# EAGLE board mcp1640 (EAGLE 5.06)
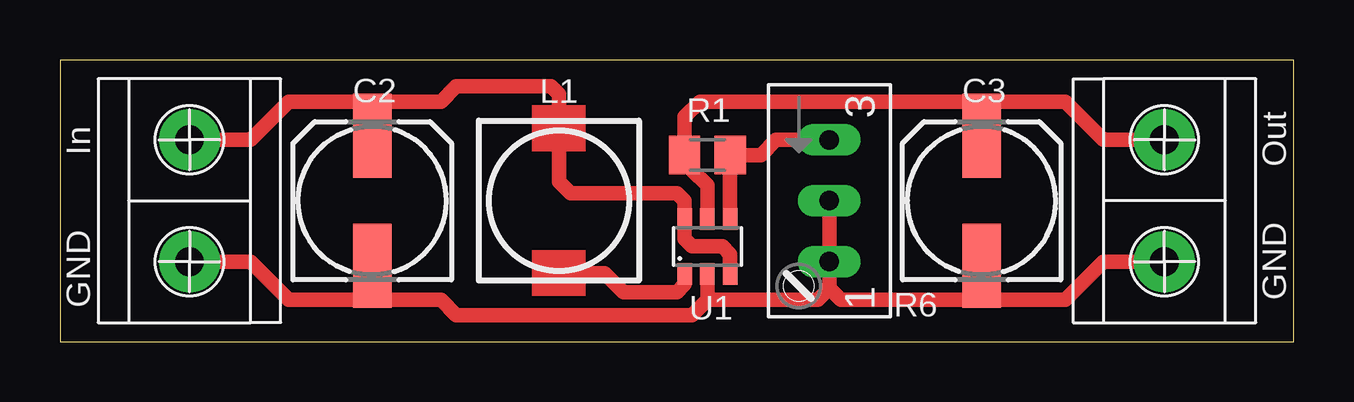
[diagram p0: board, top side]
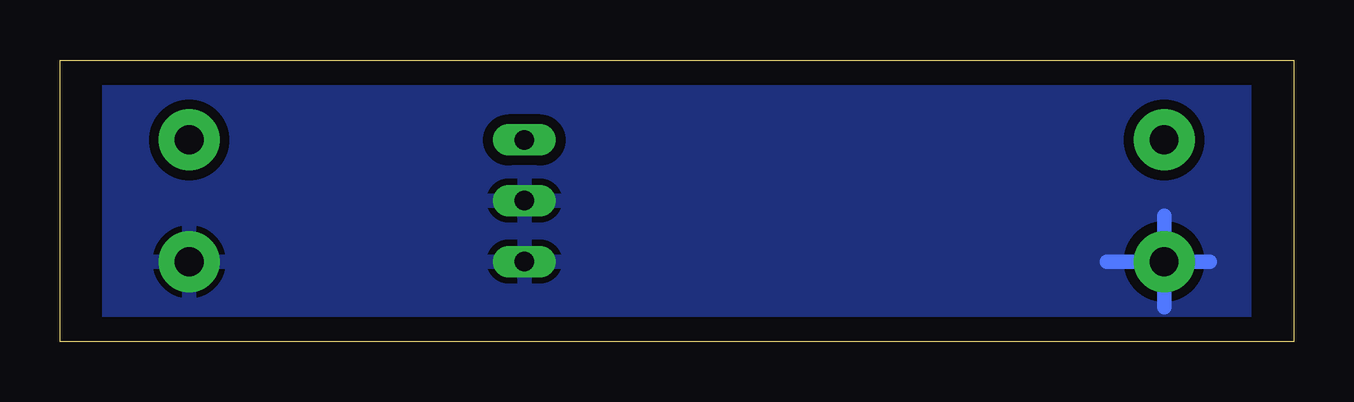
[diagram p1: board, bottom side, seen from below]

Size 51.42 x 11.74 mm. Coordinates in mm from the lower left corner, seen from the top.
Outline: 0,0 51.42,0 51.42,11.74 0,11.74 0,0
Copper layers (1*16): Top 0.035mm / dielectric 1.5mm / Bottom 0.035mm
Design rules "default": minimum track width 10mil, minimum drill 24mil, track to track 8mil, track to pad 8mil, pad to pad 8mil, via to via 8mil, smd to smd 8mil, copper to edge 40mil, drill to drill 8mil, minimum pad ring 10mil, minimum via ring 8mil, stop-mask expansion 4mil, vias tented up to drill 0mil, thermal gap 10mil

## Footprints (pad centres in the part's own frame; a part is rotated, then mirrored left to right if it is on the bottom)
153CLV-0605 = smd 3.5 x 1.6: + 2.7,0; - -2.7,0
M0805 = smd 1.3 x 1.6: 1 -0.95,0; 2 0.95,0
S64W = drill 0.813 long: A 2.54,1.27; E -2.54,1.27; S 0,1.27
SOT23-6 = smd 0.6 x 0.9: 1 -0.95,-1.15; 2 0,-1.15; 3 0.95,-1.15; 4 0.95,1.15; 5 0,1.15; 6 -0.95,1.15
ARK2 = drill 1.2 pad 2.54 round: 1 -2.54,0; 3 2.54,0 | drill 0.8 pad 2.54 round: 2 2.54,0

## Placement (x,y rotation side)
C2  4,7uF  [153CLV-0605]  13.02,5.87 90 top
C3  10uF  [153CLV-0605]  38.42,5.87 90 top
R1  1M  [M0805]  26.99,7.78 180 top
R6  1M  [S64W]  30.8,5.87 270 top
U1  93AA76A  [SOT23-6]  26.99,3.97 0 top
U$1  ARK2  [ARK2]  5.4,5.87 270 top
U$2  ARK2  [ARK2]  46.04,5.87 90 top

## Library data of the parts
C2 C3 R1 = rcl
R6 = pot
U1 = mcp1640
U$1 U$2 = ark2

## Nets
GND: C2.- C3.- R6.A R6.S U1.2 U$1.2 U$2.1
N$1: C2.+ U1.3 U1.6 U$1.1
N$2: U1.1
N$4: C3.+ R1.2 U1.5 U$2.2
N$5: R1.1 R6.E U1.4

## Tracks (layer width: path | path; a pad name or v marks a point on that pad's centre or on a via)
GND
  Top 0.61: 26.99,1.75 26.35,1.11 16.51,1.11 15.88,1.75 13.02,1.75 C2.- 13.02,2.06 12.7,1.75 9.53,1.75 7.94,3.33 U$1.2 | R6.S R6.A 32.07,2.22 | 26.99,1.75 U1.2 | 26.99,1.75 31.59,1.75 32.07,2.22 | 32.07,2.22 32.54,1.75 38.42,1.75 C3.- 38.42,2.06 38.73,1.75 41.91,1.75 43.5,3.33 U$2.1
  Bottom 0.61: U$1.2 5.4,5.24 | U$1.2 5.4,1.43 | U$1.2 7.78,3.33 | 3.49,3.33 U$1.2
  pour Bottom (isolate 0.406): 2.06,12.22 2.06,-0.48 49.37,-0.48 49.37,12.22
N$1
  Top 0.61: U1.3 27.94,3.65 27.62,3.97 26.35,3.97 26.04,4.29 U1.6 | U1.6 | 13.02,10 9.53,10 7.94,8.41 U$1.1 | U1.6 26.04,5.87 25.72,6.19 21.27,6.19 20.8,6.67 20.8,10.32 20.48,10.64 16.51,10.64 15.88,10 13.02,10 | 13.02,10 C2.+
N$2
  Top 0.61: U1.1 26.04,2.38 25.72,2.06 23.5,2.06 22.7,2.86 20.8,2.86
N$4
  Top 0.61: U1.5 26.99,6.51 26.35,7.14 26.35,7.46 R1.2 26.04,9.37 26.67,10 38.42,10 38.42,8.73 38.26,8.73 C3.+ 38.42,9.68 38.73,10 41.91,10 43.5,8.41 U$2.2
N$5
  Top 0.61: U1.4 R1.1 29.21,7.78 29.84,8.41 R6.E
(copper drawn outside any net)
  shapes: Top area x4

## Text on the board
tPlace: L1 | In | Out | GND | GND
